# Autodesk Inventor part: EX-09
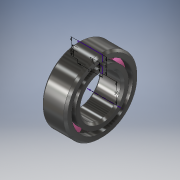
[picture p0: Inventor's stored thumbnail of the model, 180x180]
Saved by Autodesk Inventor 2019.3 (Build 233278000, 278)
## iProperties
Created: 2018-08
Part Number: EX-09
Material: Silicon Nitride
Document SubType Name: Modeling
Designer: Power User
Density: 3.18 g/cm^3
Appearance: Chrome - Polished Black
Author: Power User
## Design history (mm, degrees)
sketch "Sketch1"
  geometry: L1 (-6, 18)-(6, 18); L2 (6, 10)-(-6, 10); L3 (-6, 15)-(-2.828, 15); L4 (2.828, 15)-(6, 15); L5 (6, 13)-(2.828, 13); L6 (-2.828, 13)-(-6, 13); L7 (-6, 10)-(-6, 13); L8 (-6, 15)-(-6, 18); L9 (6, 18)-(6, 15); L10 (6, 13)-(6, 10); L11 (-16.327, 0)-(16.327, 0); L12 (0, 17)-(0, 11); A1 r 3 centre (0, 14) between (-2.828, 15) and (2.828, 15); 5 further points
  constraints: 24 end point, 9 parallel, 6 point on circle, 4 horizontal, 3 collinear, 3 midpoint, 3 vertical alignment, 2 perpendicular, 1 centre point, 1 coincident, 1 horizontal alignment, 1 vertical
  dimensions: "d4" = 12 distance of L2.start L2.end; "d5" = 8 distance of L1.end L2.start; "d6" = 10 distance from line of point (0, 0) L2; "d9" = 3 radius of A1; "d10" = 2 distance between parallel lines of L6 L3; "d11" = 3 distance between parallel lines of L2 L6; "d12" = 8 distance between parallel lines of L2 L1; "d13" = 4 distance from line of L2 A1.centre
revolve "Revolution1" stored, may be unused: angle "d14" = 90 deg
revolve "Revolution2" stored, may be unused: angle "d15" = 90 deg
pattern_circular "Circular Pattern1" dims angle "d17" = 360 deg
chamfer "Chamfer1" distance "d19" = 1; stored, may be unused: second distance "d20" = 2, angle "d21" = 45 deg
body "Solid1"
body "Solid2"
other parameters: "d7" = 2, "d8" = 3
